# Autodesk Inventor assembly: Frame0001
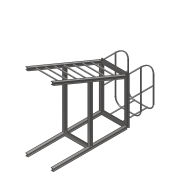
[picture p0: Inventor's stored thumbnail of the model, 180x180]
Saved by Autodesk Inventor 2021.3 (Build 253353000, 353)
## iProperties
_FrameDoc: Frame Assembly
_Version: 25.0.0
Created: 2018-07
Part Number: Frame0001
Material: Générique
Document SubType Name: Assembly
Designer: Fabian Perrée
Mass: 508899 g
Surface Area: 186744 cm^2
Volume: 64827.9 cm^3
Density: 7.85 g/cm^3
Author: Fabian Perrée
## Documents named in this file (36)
- C:\Users\Fabian\Google Drive\04_CAO-DAO\01_Exercices\01_Inventor\01_Fichiers_exercice_Inventor\01_Definitif\Frame Generator\Frame\Frame0001.iam
- C:\Users\Fabian\Google Drive\04_CAO-DAO\01_Exercices\01_Inventor\01_Fichiers_exercice_Inventor\01_Definitif\Frame Generator\Frame\Skeleton0001.ipt
- C:\Users\Fabian\Google Drive\04_CAO-DAO\01_Exercices\01_Inventor\01_Fichiers_exercice_Inventor\01_Definitif\Frame Generator\Frame\ISO SC 100 00000001.ipt
- ISO SC 100 00000001.ipt
- C:\Users\Fabian\Google Drive\04_CAO-DAO\01_Exercices\01_Inventor\01_Fichiers_exercice_Inventor\01_Definitif\Frame Generator\Frame\ISO SC 100 00000002.ipt
- ISO SC 100 00000002.ipt
- C:\Users\Fabian\Google Drive\04_CAO-DAO\01_Exercices\01_Inventor\01_Fichiers_exercice_Inventor\01_Definitif\Frame Generator\Frame\ISO SC 100 00000003.ipt
- ISO SC 100 00000003.ipt
- C:\Users\Fabian\Google Drive\04_CAO-DAO\01_Exercices\01_Inventor\01_Fichiers_exercice_Inventor\01_Definitif\Frame Generator\Frame\ISO SC 100 00000006.ipt
- ISO SC 100 00000006.ipt
- C:\Users\Fabian\Google Drive\04_CAO-DAO\01_Exercices\01_Inventor\01_Fichiers_exercice_Inventor\01_Definitif\Frame Generator\Frame\ISO 48.3x2.0 00000010.ipt
- ISO 48.3x2.0 00000010.ipt
- C:\Users\Fabian\Google Drive\04_CAO-DAO\01_Exercices\01_Inventor\01_Fichiers_exercice_Inventor\01_Definitif\Frame Generator\Frame\ISO 48.3x2.0 00000011.ipt
- ISO 48.3x2.0 00000011.ipt
- C:\Users\Fabian\Google Drive\04_CAO-DAO\01_Exercices\01_Inventor\01_Fichiers_exercice_Inventor\01_Definitif\Frame Generator\Frame\ISO 48.3x2.0 00000012.ipt
- ISO 48.3x2.0 00000012.ipt
- C:\Users\Fabian\Google Drive\04_CAO-DAO\01_Exercices\01_Inventor\01_Fichiers_exercice_Inventor\01_Definitif\Frame Generator\Frame\ISO 48.3x2.0 00000013.ipt
- ISO 48.3x2.0 00000013.ipt
- C:\Users\Fabian\Google Drive\04_CAO-DAO\01_Exercices\01_Inventor\01_Fichiers_exercice_Inventor\01_Definitif\Frame Generator\Frame\ISO 48.3x2.0 00000014.ipt
- ISO 48.3x2.0 00000014.ipt
- C:\Users\Fabian\Google Drive\04_CAO-DAO\01_Exercices\01_Inventor\01_Fichiers_exercice_Inventor\01_Definitif\Frame Generator\Frame\ISO 48.3x2.0 00000015.ipt
- ISO 48.3x2.0 00000015.ipt
- C:\Users\Fabian\Google Drive\04_CAO-DAO\01_Exercices\01_Inventor\01_Fichiers_exercice_Inventor\01_Definitif\Frame Generator\Frame\ISO 48.3x2.0 00000016.ipt
- ISO 48.3x2.0 00000016.ipt
- C:\Users\Fabian\Google Drive\04_CAO-DAO\01_Exercices\01_Inventor\01_Fichiers_exercice_Inventor\01_Definitif\Frame Generator\Frame\ISO SC 100 00000018.ipt
- ISO SC 100 00000018.ipt
- C:\Users\Fabian\Google Drive\04_CAO-DAO\01_Exercices\01_Inventor\01_Fichiers_exercice_Inventor\01_Definitif\Frame Generator\Frame\ISO SC 100 00000019.ipt
- ISO SC 100 00000019.ipt
- C:\Users\Fabian\Google Drive\04_CAO-DAO\01_Exercices\01_Inventor\01_Fichiers_exercice_Inventor\01_Definitif\Frame Generator\Frame\ISO 48.3x2.0 00000021.ipt
- ISO 48.3x2.0 00000021.ipt
- C:\Users\Fabian\Google Drive\04_CAO-DAO\01_Exercices\01_Inventor\01_Fichiers_exercice_Inventor\01_Definitif\Frame Generator\Frame\ISO 48.3x2.0 00000022.ipt
- ISO 48.3x2.0 00000022.ipt
- C:\Users\Fabian\Google Drive\04_CAO-DAO\01_Exercices\01_Inventor\01_Fichiers_exercice_Inventor\01_Definitif\Frame Generator\Frame\ISO 48.3x2.0 00000027.ipt
- ISO 48.3x2.0 00000027.ipt
- C:\Users\Fabian\Google Drive\04_CAO-DAO\01_Exercices\01_Inventor\01_Fichiers_exercice_Inventor\01_Definitif\Frame Generator\Frame\ISO 48.3x2.0 00000028.ipt
- ISO 48.3x2.0 00000028.ipt
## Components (29 placed, 18 different names)
1. Modèle de référence de l'ossature
2. ISO 48.3x2.0 00000010:1
3. ISO 48.3x2.0 00000011:1
4. ISO 48.3x2.0 00000012:1
5. ISO 48.3x2.0 00000013:1
6. ISO 48.3x2.0 00000014:1
7. ISO 48.3x2.0 00000015:1
8. ISO 48.3x2.0 00000016:1
9. ISO 657/16 SC 100 - 997:1
10. ISO 48.3x2.0 00000021:1
11. ISO 48.3x2.0 00000022:1
12. ISO 48.3x2.0 00000027:1
13. ISO 48.3x2.0 00000027:2
14. ISO 48.3x2.0 00000027:3
15. ISO 48.3x2.0 00000027:4
16. ISO 48.3x2.0 00000028:1
17. ISO 48.3x2.0 00000028:2
18. ISO 48.3x2.0 00000028:3
19. ISO 48.3x2.0 00000028:4
20. ISO SC 100 00000006:1
21. ISO SC 100 00000006:2
22. ISO SC 100 00000018:1
23. ISO SC 100 00000018:2
24. ISO SC 100 00000001:1
25. ISO SC 100 00000001:2
26. ISO SC 100 00000002:1
27. ISO SC 100 00000002:2
28. ISO SC 100 00000003:1
29. ISO SC 100 00000003:2
